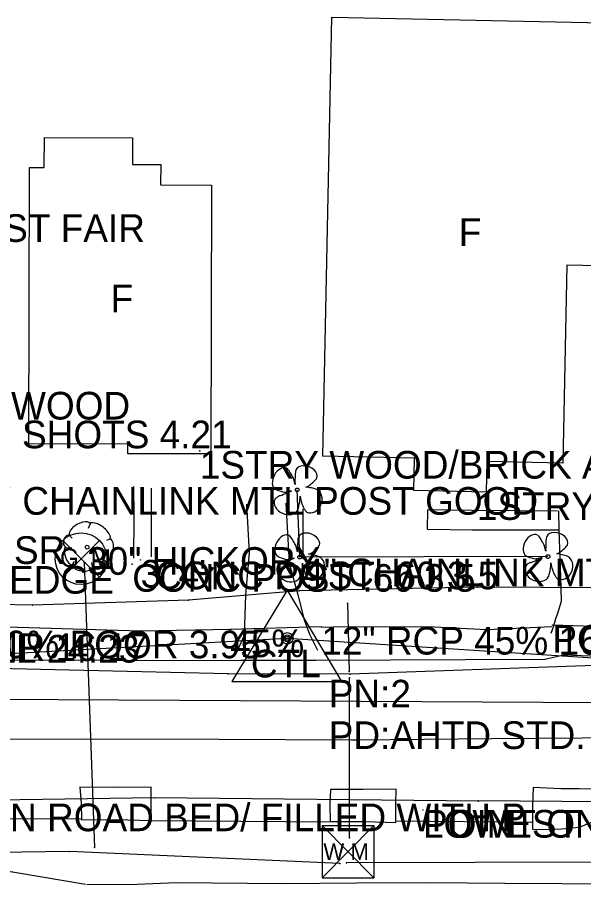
# Model space of a CAD drawing. Extents: x 1304270 to 1306561, y 1876019 to 1876752.
# Drawn here: x 1305424.7 to 1305527.1, y 1876380.4 to 1876537.2 of the extents above; entities that cross this region are included whole.
import ezdxf

# ---------------------------------------------------------------- set-up
doc = ezdxf.new("R2010")
doc.units = 0
for name, color, linetype in [('Default', 7, 'Continuous'), ('S_BUILDING', 7, 'Continuous'), ('S_BUILDING_ANNOT', 7, 'Continuous'), ('S_CROSS_DRAIN_ANNOT', 7, 'Continuous'), ('S_DITCHLINE', 7, 'Continuous'), ('S_DRG_PT_SYM', 7, 'Continuous'), ('S_DRIVEWAY', 7, 'Continuous'), ('S_EDGE_CONCRETE', 7, 'Continuous'), ('S_EDGE_PAVEMENT', 7, 'Continuous'), ('S_ELECTRIC_UTILITIES_ANNOT', 7, 'Continuous'), ('S_FENCE', 7, 'Continuous'), ('S_FENCE_ANNOT', 7, 'Continuous'), ('S_FIBER_OPTIC_CABLE', 7, 'Continuous'), ('S_GAS_UTILITIES', 7, 'Continuous'), ('S_GATE_ANNOT', 7, 'Continuous'), ('S_MISC_STRUCTURES_ANNOT', 7, 'Continuous'), ('S_MSC_PT_SYM', 7, 'Continuous'), ('S_PAVEMENT_CROWN', 7, 'Continuous'), ('S_PRIMARY_CTL', 7, 'Continuous'), ('S_PRIMARY_CTL_ANNOT', 7, 'Continuous'), ('S_SANITARY_SEWER', 7, 'Continuous'), ('S_SHOULDER', 7, 'Continuous'), ('S_SIDE_DRAIN', 7, 'Continuous'), ('S_SIDE_DRAIN_ANNOT', 7, 'Continuous'), ('S_SIDEWALK', 7, 'Continuous'), ('S_SURVEY_TEXT_ANNOT', 7, 'Continuous'), ('S_TREE', 7, 'Continuous'), ('S_TREE_ANNOT', 7, 'Continuous'), ('S_UTL_PT_SYM', 7, 'Continuous'), ('S_WATER_UTILITIES', 7, 'Continuous')]:
    doc.layers.add(name, color=color, linetype=linetype)

msp = doc.modelspace()

# ---------------------------------------------------------------- linework, layer by layer
at = {"layer": 'Default'}
for p, q in [((1304873.94, 1876392.06), (1305473.53, 1876424.94)), ((1305473.53, 1876424.94), (1305993.25, 1876391.55))]:
    msp.add_line(p, q, dxfattribs=at)
at = {"layer": 'S_BUILDING'}
for points in [[(1305479.97, 1876457.85), (1305481.58, 1876537.18), (1305536.46, 1876536.07), (1305535.57, 1876492.14), (1305524.09, 1876492.37), (1305523.36, 1876456.62), (1305509.6, 1876456.9), (1305509.49, 1876451.36), (1305496.42, 1876451.63), (1305496.54, 1876457.52)], [(1305459.82, 1876506.87), (1305459.69, 1876458.27), (1305444.68, 1876458.31), (1305444.69, 1876460.06), (1305426.82, 1876460.11), (1305426.95, 1876510.06), (1305429.61, 1876510.05), (1305429.62, 1876515.44), (1305445.58, 1876515.4), (1305445.56, 1876510.61), (1305450.65, 1876510.6), (1305450.64, 1876506.9)]]:
    msp.add_lwpolyline(points, close=True, dxfattribs=at)
at = {"layer": 'S_DITCHLINE'}
for points in [[(1305387.88, 1876426.25), (1305403.27, 1876426.7), (1305418.67, 1876427.16), (1305432.81, 1876426.73), (1305446.96, 1876426.3), (1305463.4, 1876426.58)], [(1305479.81, 1876426.98), (1305481.88, 1876427.03), (1305498.96, 1876427.09), (1305509.6, 1876426.56), (1305521.38, 1876427.08)]]:
    msp.add_lwpolyline(points, dxfattribs=at)
at = {"layer": 'S_DRG_PT_SYM'}
for points in [[(1305479.68, 1876427.01), (1305479.68, 1876427.06), (1305479.68, 1876427.01), (1305479.63, 1876427.01), (1305479.68, 1876427.01), (1305479.68, 1876426.96), (1305479.68, 1876427.01), (1305479.73, 1876427.01)], [(1305521.46, 1876427.34), (1305521.46, 1876427.39), (1305521.46, 1876427.34), (1305521.41, 1876427.34), (1305521.46, 1876427.34), (1305521.46, 1876427.29), (1305521.46, 1876427.34), (1305521.51, 1876427.34)], [(1305463.22, 1876426.54), (1305463.22, 1876426.59), (1305463.22, 1876426.54), (1305463.17, 1876426.54), (1305463.22, 1876426.54), (1305463.22, 1876426.49), (1305463.22, 1876426.54), (1305463.27, 1876426.54)]]:
    msp.add_lwpolyline(points, dxfattribs=at)
at = {"layer": 'S_DRIVEWAY'}
for points in [[(1305464.24, 1876422.1), (1305465.82, 1876425.53), (1305466.07, 1876432.82), (1305466.69, 1876440.4), (1305466.22, 1876449.21)], [(1305473.27, 1876449.36), (1305473.85, 1876438.51), (1305475.42, 1876432.81), (1305476.59, 1876428.27), (1305477.56, 1876425.71), (1305478.98, 1876422.8)], [(1305521.27, 1876425.9), (1305521.72, 1876427.19), (1305522.07, 1876428.53), (1305522.38, 1876429.28), (1305523.12, 1876431.65), (1305523, 1876436.07), (1305522.68, 1876444.45), (1305522.65, 1876448)]]:
    msp.add_lwpolyline(points, dxfattribs=at)
at = {"layer": 'S_EDGE_CONCRETE'}
for points in [[(1305436.36, 1876392.14), (1305442.63, 1876392.19), (1305448.89, 1876392.01), (1305448.9, 1876394.99), (1305448.95, 1876398.01), (1305442.87, 1876397.96), (1305436.02, 1876398.06), (1305436.26, 1876395.1)], [(1305481.29, 1876391.86), (1305487.58, 1876391.84), (1305493.16, 1876391.68), (1305493.15, 1876394.91), (1305493.19, 1876397.68), (1305487.24, 1876397.62), (1305481.37, 1876397.64), (1305481.22, 1876394.89)], [(1305517.87, 1876390.42), (1305520.39, 1876390.41), (1305523.12, 1876390.49), (1305526.37, 1876390.81), (1305528.41, 1876391.65), (1305532.63, 1876391.7), (1305533.75, 1876391.41), (1305534.32, 1876391.63), (1305535.21, 1876394.24), (1305535.21, 1876395.11), (1305534.83, 1876395.88), (1305533.28, 1876397.16), (1305532.25, 1876397.62), (1305530.37, 1876397.69), (1305526.25, 1876397.73), (1305523.02, 1876397.76), (1305517.97, 1876397.98), (1305517.88, 1876394.59)]]:
    msp.add_lwpolyline(points, close=True, dxfattribs=at)
at = {"layer": 'S_EDGE_PAVEMENT'}
for points in [[(1305388.38, 1876420.94), (1305412.9, 1876420.99), (1305437.42, 1876421.04), (1305451.62, 1876420.93), (1305465.15, 1876420.97), (1305478.67, 1876421.01), (1305492.19, 1876421.05), (1305505.71, 1876421.09), (1305520.11, 1876421.2), (1305523.54, 1876421.95), (1305534.76, 1876421.53), (1305559.32, 1876421.96), (1305583.88, 1876422.38), (1305606.66, 1876422.73)], [(1305417.16, 1876392.4), (1305436.21, 1876392.32)], [(1305449.05, 1876392.03), (1305465.11, 1876391.9), (1305481.17, 1876391.78)], [(1305493.31, 1876391.94), (1305517.73, 1876391.71)]]:
    msp.add_lwpolyline(points, dxfattribs=at)
at = {"layer": 'S_FENCE'}
msp.add_line((1305476.42, 1876439.35), (1305476.43, 1876448.25), dxfattribs=at)
msp.add_lwpolyline([(1305476.42, 1876439.35), (1305476.43, 1876448.25)], dxfattribs=at)
msp.add_lwpolyline([(1305476.42, 1876439.35), (1305476.43, 1876448.25)], dxfattribs=at)
at = {"layer": 'S_FIBER_OPTIC_CABLE'}
for p, q in [((1305475.7, 1876433.54), (1305455.68, 1876431.82)), ((1305507.97, 1876434.21), (1305475.7, 1876433.54)), ((1305536.77, 1876434.03), (1305507.97, 1876434.21)), ((1305455.68, 1876431.82), (1305427.49, 1876430.96)), ((1305427.49, 1876430.96), (1305399.24, 1876431.39)), ((1305449.61, 1876396.12), (1305404.56, 1876395.44)), ((1305508.11, 1876395.53), (1305449.61, 1876396.12)), ((1305588.12, 1876394.97), (1305508.02, 1876395.58)), ((1305508.02, 1876395.58), (1305508.11, 1876395.53))]:
    msp.add_line(p, q, dxfattribs=at)
at = {"layer": 'S_GAS_UTILITIES'}
for p, q in [((1305432.95, 1876436.01), (1305439.57, 1876442.63)), ((1305432.95, 1876442.63), (1305439.57, 1876436.01)), ((1305436.84, 1876438.67), (1305438.71, 1876387.15)), ((1305434.19, 1876386.43), (1305396.85, 1876385.91)), ((1305483.05, 1876384.26), (1305434.19, 1876386.43)), ((1305541.16, 1876384.5), (1305484.25, 1876384.34))]:
    msp.add_line(p, q, dxfattribs=at)
msp.add_circle((1305436.26, 1876439.32), 4.68, dxfattribs=at)
at = {"layer": 'S_MSC_PT_SYM'}
for points in [[(1305457.72, 1876458.81), (1305457.72, 1876458.86), (1305457.72, 1876458.81), (1305457.67, 1876458.81), (1305457.72, 1876458.81), (1305457.72, 1876458.76), (1305457.72, 1876458.81), (1305457.77, 1876458.81)], [(1305507.8, 1876451.35), (1305507.8, 1876451.4), (1305507.8, 1876451.35), (1305507.75, 1876451.35), (1305507.8, 1876451.35), (1305507.8, 1876451.3), (1305507.8, 1876451.35), (1305507.85, 1876451.35)], [(1305476.43, 1876448.25), (1305476.43, 1876448.3), (1305476.43, 1876448.25), (1305476.38, 1876448.25), (1305476.43, 1876448.25), (1305476.43, 1876448.2), (1305476.43, 1876448.25), (1305476.48, 1876448.25)], [(1305476.42, 1876439.35), (1305476.42, 1876439.4), (1305476.42, 1876439.35), (1305476.37, 1876439.35), (1305476.42, 1876439.35), (1305476.42, 1876439.3), (1305476.42, 1876439.35), (1305476.47, 1876439.35)], [(1305445.5, 1876438.36), (1305445.5, 1876438.41), (1305445.5, 1876438.36), (1305445.45, 1876438.36), (1305445.5, 1876438.36), (1305445.5, 1876438.31), (1305445.5, 1876438.36), (1305445.55, 1876438.36)], [(1305447.02, 1876439.11), (1305447.02, 1876439.16), (1305447.02, 1876439.11), (1305446.97, 1876439.11), (1305447.02, 1876439.11), (1305447.02, 1876439.06), (1305447.02, 1876439.11), (1305447.07, 1876439.11)], [(1305449.63, 1876438.81), (1305449.63, 1876438.86), (1305449.63, 1876438.81), (1305449.58, 1876438.81), (1305449.63, 1876438.81), (1305449.63, 1876438.76), (1305449.63, 1876438.81), (1305449.68, 1876438.81)], [(1305498.07, 1876393.92), (1305498.07, 1876393.97), (1305498.07, 1876393.92), (1305498.02, 1876393.92), (1305498.07, 1876393.92), (1305498.07, 1876393.87), (1305498.07, 1876393.92), (1305498.12, 1876393.92)]]:
    msp.add_lwpolyline(points, dxfattribs=at)
at = {"layer": 'S_PAVEMENT_CROWN'}
msp.add_lwpolyline([(1305413.65, 1876406.71), (1305437.28, 1876406.8), (1305461.2, 1876406.7), (1305485.13, 1876406.59), (1305486.04, 1876406.61), (1305510.54, 1876406.81), (1305535.03, 1876407.01), (1305559.9, 1876406.97), (1305584.78, 1876406.94), (1305605.66, 1876407.25)], dxfattribs=at)
at = {"layer": 'S_PRIMARY_CTL'}
for p, q in [((1305473.53, 1876433.64), (1305463.5, 1876417.13)), ((1305473.53, 1876433.64), (1305483.36, 1876417.13)), ((1305463.5, 1876417.13), (1305483.36, 1876417.13))]:
    msp.add_line(p, q, dxfattribs=at)
for radius in [1.04, 0.609, 0.344]:
    msp.add_circle((1305473.53, 1876424.94), radius, dxfattribs=at)
at = {"layer": 'S_SANITARY_SEWER'}
msp.add_line((1305626.32, 1876412.77), (1305348.54, 1876414.26), dxfattribs=at)
at = {"layer": 'S_SHOULDER'}
for points in [[(1305437.27, 1876380.42), (1305446.39, 1876380.5), (1305453.47, 1876380.78), (1305472.77, 1876380.64), (1305486.07, 1876380.72), (1305499.38, 1876380.8), (1305512.87, 1876380.68), (1305533.51, 1876380.58), (1305533.72, 1876380.81), (1305533.8, 1876386.24), (1305533.75, 1876391.26)], [(1305370.31, 1876384.27), (1305371.53, 1876385.07), (1305385.28, 1876385.09), (1305403.11, 1876384.15), (1305420.94, 1876383.2), (1305437.03, 1876380.49)]]:
    msp.add_lwpolyline(points, dxfattribs=at)
at = {"layer": 'S_SIDE_DRAIN'}
for p, q in [((1305479.68, 1876427.01), (1305463.22, 1876426.54)), ((1305537.01, 1876426.79), (1305521.46, 1876427.34))]:
    msp.add_line(p, q, dxfattribs=at)
at = {"layer": 'S_SIDEWALK'}
for points in [[(1305445.73, 1876452.37), (1305445.78, 1876446.89), (1305445.75, 1876439.4)], [(1305448.98, 1876439.67), (1305449, 1876445.26), (1305448.96, 1876452.11)], [(1305522.4, 1876447.91), (1305507.02, 1876448.02), (1305498.87, 1876448.14), (1305498.85, 1876444.67), (1305506.95, 1876444.53), (1305522.58, 1876444.53)]]:
    msp.add_lwpolyline(points, dxfattribs=at)
at = {"layer": 'S_TREE'}
for p, q in [((1305474.96, 1876452.75), (1305474.71, 1876453.65)), ((1305476.91, 1876452.29), (1305477.28, 1876452.46)), ((1305474.31, 1876451.59), (1305473.33, 1876451.37)), ((1305475.78, 1876439.62), (1305475.33, 1876451.77)), ((1305475.84, 1876450.66), (1305475.92, 1876450.22)), ((1305437.91, 1876445.66), (1305437.52, 1876444.81)), ((1305434.11, 1876443.65), (1305434.62, 1876443.07)), ((1305441.48, 1876442.87), (1305440.82, 1876442.6)), ((1305433.45, 1876441.32), (1305434.58, 1876441.32)), ((1305475.41, 1876440.6), (1305475.17, 1876441.49)), ((1305520.29, 1876440.69), (1305520.05, 1876441.58)), ((1305474.76, 1876439.43), (1305473.79, 1876439.22)), ((1305520.66, 1876439.71), (1305475.78, 1876439.62)), ((1305477.36, 1876440.14), (1305477.74, 1876440.3)), ((1305519.64, 1876439.52), (1305518.67, 1876439.31)), ((1305522.24, 1876440.23), (1305522.62, 1876440.39)), ((1305434.62, 1876438.15), (1305435.08, 1876438.84)), ((1305438.3, 1876437.88), (1305438.22, 1876438.65)), ((1305440.7, 1876438.77), (1305440.24, 1876439.19)), ((1305476.29, 1876438.5), (1305476.37, 1876438.06)), ((1305521.18, 1876438.59), (1305521.26, 1876438.15))]:
    msp.add_line(p, q, dxfattribs=at)
for centre in [(1305475.33, 1876451.77), (1305437.35, 1876441.42), (1305475.78, 1876439.62), (1305520.66, 1876439.71)]:
    msp.add_circle(centre, 0.341, dxfattribs=at)
for centre, major_axis, ratio, start_param, end_param in [((1305472.44, 1876453.79), (-1.03, -1.88), 0.662338, 3.141593, 6.283185), ((1305474.09, 1876454.66), (0.62, -1.01), 0.083512, 0, 3.141593), ((1305475.03, 1876454.08), (-0.07, -1.33), 0.068203, 3.141593, 6.283185), ((1305476.99, 1876454.66), (1.89, -0.74), 0.673998, 0, 3.141593), ((1305478.08, 1876453.19), (-0.798, -0.73), 0.092159, 0, 3.141593), ((1305472.37, 1876451.64), (0.964, -0.267), 0.113563, 3.141593, 6.283185), ((1305477.87, 1876452.06), (0.96, -0.23), 0.056001, 0, 3.141593), ((1305477.94, 1876449.79), (0.88, 2.05), 0.81717, 3.141593, 6.283185), ((1305471.75, 1876450.38), (0.477, 0.328), 0.136309, 0, 3.141593), ((1305473.27, 1876451.15), (1.04, 0.44), 0.002756, 3.141593, 6.283185), ((1305475.61, 1876449.49), (0.19, 1.31), 0.114148, 3.141593, 5.822668), ((1305473.35, 1876449.11), (2.07, -0.93), 0.760068, 3.141593, 6.283185), ((1305476.17, 1876449.45), (0.254, -0.771), 0.051603, 3.141593, 6.283185), ((1305476.75, 1876448.21), (-0.321, 0.467), 0.094289, 0, 3.141593), ((1305436.02, 1876444.62), (1.86, 1.08), 0.471018, 0, 3.141593), ((1305439.67, 1876444.3), (-1.81, 1.36), 0.405113, 3.141593, 6.283186), ((1305477.44, 1876442.5), (1.89, -0.74), 0.673998, 0, 3.141593), ((1305517.77, 1876441.73), (-1.03, -1.88), 0.662338, 3.141593, 6.283185), ((1305522.32, 1876442.59), (1.89, -0.74), 0.673998, 0, 3.141593), ((1305433.78, 1876442.51), (0.31, 1.03), 0.646762, 0, 3.141593), ((1305441.03, 1876440.89), (0.46, 2.04), 0.482994, 3.141593, 6.283185), ((1305472.89, 1876441.64), (-1.03, -1.88), 0.662338, 3.141593, 6.283185), ((1305474.54, 1876442.5), (0.62, -1.01), 0.083512, 0, 3.141593), ((1305475.48, 1876441.92), (-0.07, -1.33), 0.068203, 3.141593, 6.283185), ((1305519.43, 1876442.59), (0.62, -1.01), 0.083512, 0, 3.141593), ((1305520.36, 1876442.01), (-0.07, -1.33), 0.068203, 3.141593, 6.283185), ((1305434.09, 1876439.86), (-0.61, 1.6), 0.420543, 6.283185, 9.424777), ((1305478.53, 1876441.03), (-0.798, -0.73), 0.092159, 0, 3.141593), ((1305523.42, 1876441.12), (-0.798, -0.73), 0.092159, 0, 3.141593), ((1305472.82, 1876439.48), (0.964, -0.267), 0.113563, 3.141593, 6.283185), ((1305473.72, 1876438.99), (1.04, 0.44), 0.002756, 3.141593, 6.283185), ((1305478.32, 1876439.91), (0.96, -0.23), 0.056001, 0, 3.141593), ((1305478.4, 1876437.63), (0.88, 2.05), 0.81717, 3.141593, 6.283185), ((1305517.71, 1876439.57), (0.964, -0.267), 0.113563, 3.141593, 6.283185), ((1305518.61, 1876439.08), (1.04, 0.44), 0.002756, 3.141593, 6.283185), ((1305523.2, 1876440), (0.96, -0.23), 0.056001, 0, 3.141593), ((1305523.28, 1876437.72), (0.88, 2.05), 0.81717, 3.141593, 6.283185), ((1305436.55, 1876438.08), (-1.83, 0.19), 0.529943, 0, 3.141593), ((1305439.5, 1876438.37), (1.09, 0.46), 0.711534, 3.141592, 6.283185), ((1305473.8, 1876436.96), (2.07, -0.93), 0.760068, 3.141593, 6.283185), ((1305472.21, 1876438.22), (0.477, 0.328), 0.136309, 0, 3.141593), ((1305476.06, 1876437.34), (0.19, 1.31), 0.114148, 3.141593, 5.822668), ((1305476.63, 1876437.29), (0.254, -0.771), 0.051603, 3.141593, 6.283185), ((1305518.68, 1876437.05), (2.07, -0.93), 0.760068, 3.141593, 6.283185), ((1305517.09, 1876438.31), (0.477, 0.328), 0.136309, 0, 3.141593), ((1305520.94, 1876437.43), (0.19, 1.31), 0.114148, 3.141593, 5.822668), ((1305521.51, 1876437.38), (0.254, -0.771), 0.051603, 3.141593, 6.283185), ((1305477.2, 1876436.06), (-0.321, 0.467), 0.094289, 0, 3.141593), ((1305522.09, 1876436.15), (-0.321, 0.467), 0.094289, 0, 3.141593)]:
    msp.add_ellipse(centre, major_axis=major_axis, ratio=ratio, start_param=start_param, end_param=end_param, dxfattribs=at)
at = {"layer": 'S_UTL_PT_SYM'}
for points in [[(1305436.84, 1876438.67), (1305436.84, 1876438.72), (1305436.84, 1876438.67), (1305436.79, 1876438.67), (1305436.84, 1876438.67), (1305436.84, 1876438.62), (1305436.84, 1876438.67), (1305436.89, 1876438.67)], [(1305475.7, 1876433.54), (1305475.7, 1876433.59), (1305475.7, 1876433.54), (1305475.65, 1876433.54), (1305475.7, 1876433.54), (1305475.7, 1876433.49), (1305475.7, 1876433.54), (1305475.75, 1876433.54)], [(1305507.97, 1876434.21), (1305507.97, 1876434.26), (1305507.97, 1876434.21), (1305507.92, 1876434.21), (1305507.97, 1876434.21), (1305507.97, 1876434.16), (1305507.97, 1876434.21), (1305508.02, 1876434.21)], [(1305455.68, 1876431.82), (1305455.68, 1876431.87), (1305455.68, 1876431.82), (1305455.63, 1876431.82), (1305455.68, 1876431.82), (1305455.68, 1876431.77), (1305455.68, 1876431.82), (1305455.73, 1876431.82)], [(1305427.49, 1876430.96), (1305427.49, 1876431.01), (1305427.49, 1876430.96), (1305427.44, 1876430.96), (1305427.49, 1876430.96), (1305427.49, 1876430.91), (1305427.49, 1876430.96), (1305427.54, 1876430.96)], [(1305484.45, 1876431.28), (1305484.45, 1876431.33), (1305484.45, 1876431.28), (1305484.4, 1876431.28), (1305484.45, 1876431.28), (1305484.45, 1876431.23), (1305484.45, 1876431.28), (1305484.5, 1876431.28)], [(1305484.73, 1876418.93), (1305484.73, 1876418.98), (1305484.73, 1876418.93), (1305484.68, 1876418.93), (1305484.73, 1876418.93), (1305484.73, 1876418.88), (1305484.73, 1876418.93), (1305484.78, 1876418.93)], [(1305462.85, 1876418.52), (1305462.85, 1876418.57), (1305462.85, 1876418.52), (1305462.8, 1876418.52), (1305462.85, 1876418.52), (1305462.85, 1876418.47), (1305462.85, 1876418.52), (1305462.9, 1876418.52)], [(1305484.77, 1876417.79), (1305484.77, 1876417.84), (1305484.77, 1876417.79), (1305484.72, 1876417.79), (1305484.77, 1876417.79), (1305484.77, 1876417.74), (1305484.77, 1876417.79), (1305484.82, 1876417.79)], [(1305484.91, 1876418.45), (1305484.91, 1876418.5), (1305484.91, 1876418.45), (1305484.86, 1876418.45), (1305484.91, 1876418.45), (1305484.91, 1876418.4), (1305484.91, 1876418.45), (1305484.96, 1876418.45)], [(1305449.61, 1876396.12), (1305449.61, 1876396.17), (1305449.61, 1876396.12), (1305449.56, 1876396.12), (1305449.61, 1876396.12), (1305449.61, 1876396.07), (1305449.61, 1876396.12), (1305449.66, 1876396.12)], [(1305508.02, 1876395.58), (1305508.02, 1876395.63), (1305508.02, 1876395.58), (1305507.96, 1876395.58), (1305508.02, 1876395.58), (1305508.02, 1876395.53), (1305508.02, 1876395.58), (1305508.06, 1876395.58)], [(1305508.11, 1876395.53), (1305508.11, 1876395.58), (1305508.11, 1876395.53), (1305508.06, 1876395.53), (1305508.11, 1876395.53), (1305508.11, 1876395.48), (1305508.11, 1876395.53), (1305508.17, 1876395.53)], [(1305498.07, 1876393.92), (1305498.07, 1876393.97), (1305498.07, 1876393.92), (1305498.02, 1876393.92), (1305498.07, 1876393.92), (1305498.07, 1876393.87), (1305498.07, 1876393.92), (1305498.12, 1876393.92)], [(1305484.8, 1876388.89), (1305484.8, 1876388.94), (1305484.8, 1876388.89), (1305484.75, 1876388.89), (1305484.8, 1876388.89), (1305484.8, 1876388.84), (1305484.8, 1876388.89), (1305484.85, 1876388.89)], [(1305434.19, 1876386.43), (1305434.19, 1876386.48), (1305434.19, 1876386.43), (1305434.14, 1876386.43), (1305434.19, 1876386.43), (1305434.19, 1876386.38), (1305434.19, 1876386.43), (1305434.24, 1876386.43)], [(1305438.71, 1876387.15), (1305438.71, 1876387.2), (1305438.71, 1876387.15), (1305438.66, 1876387.15), (1305438.71, 1876387.15), (1305438.71, 1876387.1), (1305438.71, 1876387.15), (1305438.76, 1876387.15)], [(1305484.25, 1876384.34), (1305484.25, 1876384.39), (1305484.25, 1876384.34), (1305484.2, 1876384.34), (1305484.25, 1876384.34), (1305484.25, 1876384.29), (1305484.25, 1876384.34), (1305484.3, 1876384.34)], [(1305483.05, 1876384.26), (1305483.05, 1876384.31), (1305483.05, 1876384.26), (1305483, 1876384.26), (1305483.05, 1876384.26), (1305483.05, 1876384.21), (1305483.05, 1876384.26), (1305483.1, 1876384.26)]]:
    msp.add_lwpolyline(points, dxfattribs=at)
at = {"layer": 'S_WATER_UTILITIES'}
for p, q in [((1305484.45, 1876431.28), (1305484.73, 1876418.93)), ((1305577.4, 1876421.77), (1305484.91, 1876418.45)), ((1305462.85, 1876418.52), (1305400.37, 1876420)), ((1305484.91, 1876418.45), (1305462.85, 1876418.52)), ((1305484.8, 1876388.89), (1305484.77, 1876417.79)), ((1305479.85, 1876391.13), (1305489.19, 1876391.13)), ((1305479.85, 1876391.13), (1305479.85, 1876381.64)), ((1305479.85, 1876391.13), (1305489.19, 1876381.64)), ((1305489.19, 1876391.13), (1305479.85, 1876381.64)), ((1305489.19, 1876391.13), (1305489.19, 1876381.64)), ((1305479.85, 1876381.64), (1305489.19, 1876381.64))]:
    msp.add_line(p, q, dxfattribs=at)

# ---------------------------------------------------------------- texts
at = {"layer": 'S_BUILDING_ANNOT'}
for s, p in [('F', (1305504.54, 1876495.86)), ('F', (1305441.58, 1876483.88)), ('1 STRY WOOD', (1305398.32, 1876464.49))]:
    msp.add_text(s, height=5, dxfattribs=at).set_placement(p)
at = {"layer": 'S_CROSS_DRAIN_ANNOT'}
msp.add_text('12" RCP POOR 85% FILL 24.23', height=5, dxfattribs=at).set_placement((1305350.39, 1876420.56))
at = {"layer": 'S_ELECTRIC_UTILITIES_ANNOT'}
msp.add_text('POINT ON ROAD UNDER LOW L', height=5, dxfattribs=at).set_placement((1305498.07, 1876388.92))
at = {"layer": 'S_FENCE_ANNOT'}
for s, p in [("4' CHAINLINK MTL POST FAIR", (1305352.9, 1876496.59)), ("4' CHAINLINK MTL POST GOOD", (1305418.78, 1876447.28)), ('4" CHAINLINK MTL POST GOOD', (1305476.42, 1876434.35))]:
    msp.add_text(s, height=5, dxfattribs=at).set_placement(p)
at = {"layer": 'S_GAS_UTILITIES'}
for s, p in [('G', (1305432.44, 1876437.85)), ('M', (1305438, 1876437.75))]:
    msp.add_text(s, height=3.3, rotation=360, dxfattribs=at).set_placement(p)
at = {"layer": 'S_GATE_ANNOT'}
msp.add_text("3' 4'", height=5, dxfattribs=at).set_placement((1305447.02, 1876434.11))
at = {"layer": 'S_MISC_STRUCTURES_ANNOT'}
for p in [(1305445.5, 1876433.36), (1305449.63, 1876433.81)]:
    msp.add_text('CONC POST .60 3.5', height=5, dxfattribs=at).set_placement(p)
at = {"layer": 'S_PRIMARY_CTL'}
msp.add_text('CTL', height=5, rotation=360, dxfattribs=at).set_placement((1305466.95, 1876417.87))
at = {"layer": 'S_PRIMARY_CTL_ANNOT'}
for s, p in [('PN:2', (1305481.03, 1876412.44)), ('PD:AHTD STD. MONUMENT STAMPED PN:2', (1305481.03, 1876404.94))]:
    msp.add_text(s, height=5, dxfattribs=at).set_placement(p)
at = {"layer": 'S_SIDE_DRAIN_ANNOT'}
for s, p in [('12" RCP 25% FAIR DEL ABOVE SHOTS 4.21', (1305325.84, 1876459.29)), ('12" RCP 45% 16.46', (1305479.68, 1876422.01)), ('POOR 85% FILL', (1305521.46, 1876422.34)), ('12" RCP 85% FAIR 16.17', (1305371.66, 1876420.84)), ('12" RCP 100% POOR 3.95', (1305387.58, 1876421.33)), ('45%', (1305463.22, 1876421.54))]:
    msp.add_text(s, height=5, dxfattribs=at).set_placement(p)
at = {"layer": 'S_SURVEY_TEXT_ANNOT'}
for s, p in [('1STRY WOOD/BRICK ABANDON BU', (1305457.72, 1876453.81)), ('1STRY BRICK/WOOD BU', (1305507.8, 1876446.35)), ('HOLE IN ROAD BED/ FILLED WITH P', (1305401.49, 1876390.08)), ('LOWEST UTILITY LINE', (1305498.07, 1876388.92))]:
    msp.add_text(s, height=5, dxfattribs=at).set_placement(p)
at = {"layer": 'S_TREE_ANNOT'}
for s, p in [('MULTI BASED SR', (1305377.68, 1876438.39)), ('30" HICKORY', (1305437.35, 1876436.42)), ('PREVIT HEDGE', (1305392.41, 1876433.01))]:
    msp.add_text(s, height=5, dxfattribs=at).set_placement(p)
at = {"layer": 'S_WATER_UTILITIES'}
msp.add_text('W M', height=3, rotation=360, dxfattribs=at).set_placement((1305480.05, 1876384.9))

doc.saveas('drawing.dxf')
